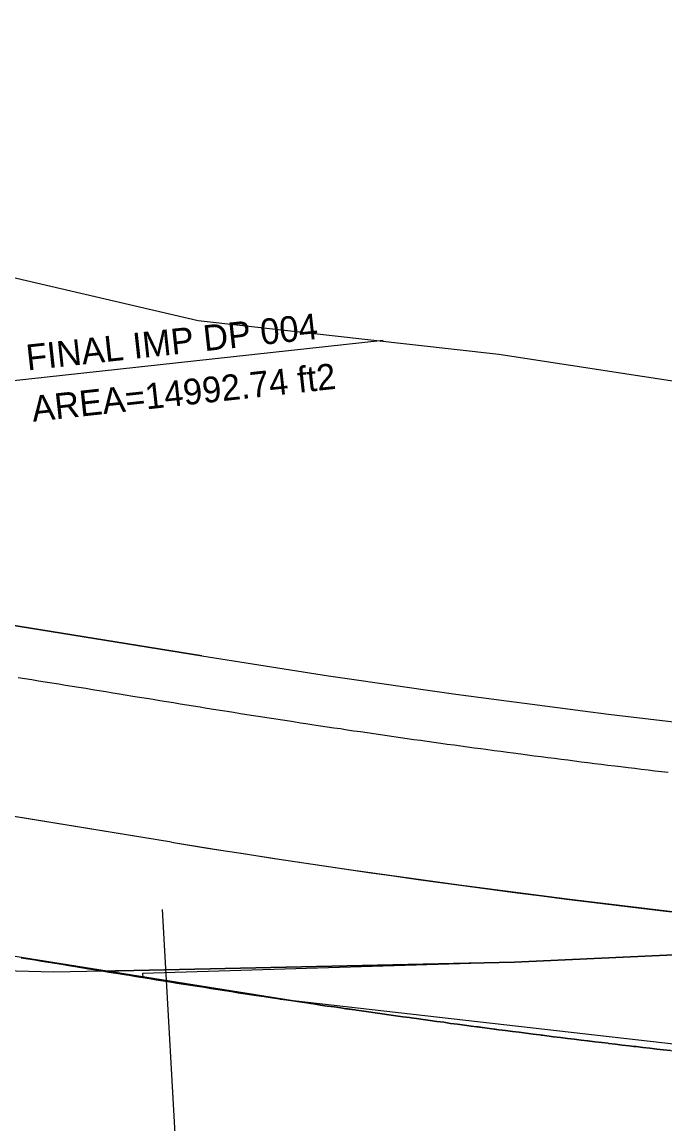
# Model space of a CAD drawing. Extents: x 1509538 to 1510847, y 401283 to 402022.
# Drawn here: x 1510416.9 to 1510486.8, y 401644.9 to 401764.5 of the extents above; entities that cross this region are included whole.
import ezdxf

# ---------------------------------------------------------------- set-up
doc = ezdxf.new("R2010")
doc.units = 0
for name, color, linetype in [('LDEFAULT_P', 7, 'Continuous'), ('Level 14', 7, 'Continuous'), ('Level 19', 7, 'Continuous'), ('Level 2', 7, 'Continuous'), ('Level 20', 7, 'Continuous'), ('Level 23', 7, 'Continuous'), ('Level 24', 7, 'Continuous'), ('Level 3', 7, 'Continuous'), ('Level 4', 7, 'Continuous')]:
    doc.layers.add(name, color=color, linetype=linetype)

msp = doc.modelspace()

# ---------------------------------------------------------------- linework, layer by layer
at = {"layer": 'LDEFAULT_P'}
for points in [[(1510353.52, 401708.78), (1510415.34, 401725.51), (1510456.17, 401729.97)], [(1510432.16, 401668.14), (1510435.57, 401607.93), (1510476.4, 401612.38)]]:
    msp.add_lwpolyline(points, dxfattribs=at)
at = {"layer": 'Level 14'}
for p, q in [((1510311.33, 401716), (1510436.45, 401695.69)), ((1510433.17, 401675.46), (1510308.05, 401695.77))]:
    msp.add_line(p, q, dxfattribs=at)
for centre, radius, start, end in [((1510625.43, 402859.96), 1179.5, 260.78048, 265.11677), ((1510626.3, 402875.58), 1215.57, 260.85794, 272.75803)]:
    msp.add_arc(centre, radius, start, end, dxfattribs=at)
at = {"layer": 'Level 19'}
for points in [[(1510433.17, 401675.46), (1510410.94, 401679.07)], [(1510425.8, 401661.46), (1510470.43, 401662.43), (1510519.22, 401664.67)], [(1510416.84, 401662.91), (1510417.58, 401662.79), (1510418.31, 401662.67), (1510419.04, 401662.55), (1510419.78, 401662.43), (1510420.51, 401662.32), (1510421.24, 401662.2), (1510421.97, 401662.08), (1510422.71, 401661.96), (1510423.34, 401661.86), (1510424.17, 401661.72), (1510424.91, 401661.6), (1510425.8, 401661.46), (1510425.8, 401661.46)]]:
    msp.add_lwpolyline(points, dxfattribs=at)
msp.add_arc((1510625.43, 402859.96), 1200, 260.78048, 264.92169, dxfattribs=at)
at = {"layer": 'Level 2'}
for p, q in [((1510425.8, 401661.46), (1510426.37, 401661.36)), ((1510430.02, 401661.19), (1510430.04, 401660.77)), ((1510432.25, 401660.41), (1510433, 401660.29)), ((1510433, 401660.29), (1510433.74, 401660.17)), ((1510433.74, 401660.17), (1510434.48, 401660.05)), ((1510435.97, 401659.82), (1510436.71, 401659.7)), ((1510436.71, 401659.7), (1510437.45, 401659.58)), ((1510437.45, 401659.58), (1510438.2, 401659.47)), ((1510438.2, 401659.47), (1510438.94, 401659.35)), ((1510438.94, 401659.35), (1510439.68, 401659.24)), ((1510443.25, 401658.69), (1510444.14, 401658.56)), ((1510444.14, 401658.56), (1510444.88, 401658.45)), ((1510446.37, 401658.22), (1510447.11, 401658.11)), ((1510447.11, 401658.11), (1510447.86, 401658)), ((1510447.86, 401658), (1510448.6, 401657.89)), ((1510452.09, 401657.38), (1510453.07, 401657.24)), ((1510458.28, 401656.51), (1510459.02, 401656.41)), ((1510459.02, 401656.41), (1510459.77, 401656.3)), ((1510459.77, 401656.3), (1510460.51, 401656.2)), ((1510460.51, 401656.2), (1510461.26, 401656.1)), ((1510463.29, 401655.82), (1510464.24, 401655.69)), ((1510465.73, 401655.5), (1510466.34, 401655.42)), ((1510466.34, 401655.42), (1510467.22, 401655.3)), ((1510467.22, 401655.3), (1510467.96, 401655.2)), ((1510467.96, 401655.2), (1510468.71, 401655.1)), ((1510471.69, 401654.72), (1510472.44, 401654.63)), ((1510472.44, 401654.63), (1510473.18, 401654.53)), ((1510477.66, 401653.97), (1510478.36, 401653.89)), ((1510479.9, 401653.7), (1510480.61, 401653.62)), ((1510480.61, 401653.62), (1510481.39, 401653.52)), ((1510482.89, 401653.35), (1510483.63, 401653.26))]:
    msp.add_line(p, q, dxfattribs=at)
for points in [[(1510621.58, 401670.53), (1510593.1, 401669.05), (1510591.76, 401675.43), (1510572.55, 401675.82), (1510570.33, 401679.6), (1510568.49, 401681.42), (1510567.15, 401683.24), (1510565.64, 401686.29), (1510548.91, 401687.45), (1510550.67, 401678.74), (1510543.3, 401672.37), (1510525.32, 401669.96), (1510520.33, 401664.72), (1510470.43, 401662.43), (1510425.8, 401661.46)], [(1510520.33, 401664.72), (1510470.43, 401662.43), (1510430.02, 401661.19)], [(1510426.37, 401661.36), (1510427.11, 401661.24), (1510427.84, 401661.13), (1510428.28, 401661.05), (1510428.57, 401661.01), (1510429.3, 401660.89), (1510430.04, 401660.77), (1510430.77, 401660.65), (1510430.77, 401660.65), (1510431.51, 401660.53), (1510432.25, 401660.41), (1510433, 401660.29), (1510433.24, 401660.25), (1510433.74, 401660.17), (1510434.48, 401660.05), (1510435.22, 401659.94), (1510435.97, 401659.82), (1510436.71, 401659.7), (1510437.45, 401659.58), (1510437.87, 401659.52), (1510438.2, 401659.47), (1510438.24, 401659.46), (1510438.94, 401659.35), (1510439.68, 401659.24), (1510440.42, 401659.12), (1510441.17, 401659.01), (1510441.91, 401658.9), (1510442.65, 401658.78), (1510443.25, 401658.69), (1510443.4, 401658.67), (1510444.14, 401658.56), (1510444.88, 401658.45), (1510444.98, 401658.43), (1510445.63, 401658.33), (1510446.37, 401658.22), (1510447.11, 401658.11), (1510447.86, 401658), (1510448.26, 401657.94), (1510448.6, 401657.89), (1510449.35, 401657.78), (1510450.09, 401657.67), (1510450.83, 401657.57), (1510451.58, 401657.46), (1510452.09, 401657.38), (1510452.32, 401657.35), (1510453.07, 401657.24), (1510453.27, 401657.22), (1510453.81, 401657.14), (1510454.56, 401657.03), (1510455.3, 401656.93), (1510456.04, 401656.82), (1510456.79, 401656.72), (1510457.53, 401656.61), (1510458.28, 401656.51), (1510459.02, 401656.41), (1510459.21, 401656.38), (1510459.77, 401656.3), (1510460.51, 401656.2), (1510461.26, 401656.1), (1510462, 401656), (1510462.75, 401655.9), (1510463.29, 401655.82), (1510463.49, 401655.79), (1510464.24, 401655.69), (1510464.98, 401655.6), (1510465.73, 401655.5), (1510466.34, 401655.42), (1510466.47, 401655.4), (1510467.22, 401655.3), (1510467.96, 401655.2), (1510468.31, 401655.16), (1510468.71, 401655.1), (1510469.46, 401655.01), (1510470.2, 401654.91), (1510470.95, 401654.82), (1510471.69, 401654.72), (1510472.44, 401654.63), (1510473.18, 401654.53), (1510473.33, 401654.51), (1510473.47, 401654.5), (1510473.93, 401654.44), (1510474.68, 401654.34), (1510475.42, 401654.25), (1510476.17, 401654.16), (1510476.92, 401654.07), (1510477.66, 401653.97), (1510478.36, 401653.89), (1510478.41, 401653.88), (1510479.15, 401653.79), (1510479.9, 401653.7), (1510480.61, 401653.62), (1510480.65, 401653.61), (1510481.39, 401653.52), (1510482.14, 401653.43), (1510482.89, 401653.35), (1510483.38, 401653.29), (1510483.63, 401653.26), (1510484.38, 401653.17), (1510485.13, 401653.08), (1510485.87, 401653), (1510486.62, 401652.91), (1510487.37, 401652.83)], [(1510430.04, 401660.77), (1510430.77, 401660.65), (1510431.51, 401660.53), (1510432.25, 401660.41)], [(1510434.48, 401660.05), (1510435.22, 401659.94), (1510435.97, 401659.82)], [(1510439.68, 401659.24), (1510440.42, 401659.12), (1510441.17, 401659.01), (1510441.91, 401658.9)], [(1510441.91, 401658.9), (1510442.65, 401658.78), (1510443.25, 401658.69)], [(1510444.88, 401658.45), (1510445.63, 401658.33), (1510446.37, 401658.22)], [(1510448.6, 401657.89), (1510449.35, 401657.78), (1510450.09, 401657.67), (1510450.83, 401657.57), (1510451.58, 401657.46), (1510452.09, 401657.38)], [(1510453.07, 401657.24), (1510453.81, 401657.14), (1510454.56, 401657.03), (1510455.3, 401656.93), (1510456.04, 401656.82)], [(1510456.04, 401656.82), (1510456.79, 401656.72), (1510457.53, 401656.61), (1510458.28, 401656.51)], [(1510461.26, 401656.1), (1510462, 401656), (1510462.75, 401655.9), (1510463.29, 401655.82)], [(1510464.24, 401655.69), (1510464.98, 401655.6), (1510465.73, 401655.5)], [(1510468.71, 401655.1), (1510469.46, 401655.01), (1510470.2, 401654.91), (1510470.95, 401654.82), (1510471.69, 401654.72)], [(1510473.18, 401654.53), (1510473.93, 401654.44), (1510474.68, 401654.34)], [(1510474.68, 401654.34), (1510475.42, 401654.25), (1510476.17, 401654.16)], [(1510476.17, 401654.16), (1510476.92, 401654.07), (1510477.66, 401653.97)], [(1510478.36, 401653.89), (1510479.15, 401653.79), (1510479.9, 401653.7)], [(1510481.39, 401653.52), (1510482.14, 401653.43), (1510482.89, 401653.35)], [(1510483.63, 401653.26), (1510484.38, 401653.17), (1510485.13, 401653.08), (1510485.87, 401653), (1510486.62, 401652.91), (1510487.37, 401652.83), (1510488.11, 401652.74)]]:
    msp.add_lwpolyline(points, dxfattribs=at)
at = {"layer": 'Level 20'}
msp.add_line((1510425.8, 401661.46), (1510426.37, 401661.36), dxfattribs=at)
for points in [[(1510519.22, 401664.67), (1510470.43, 401662.43), (1510425.8, 401661.46)], [(1510426.37, 401661.36), (1510427.11, 401661.24), (1510427.84, 401661.13), (1510428.28, 401661.05), (1510428.57, 401661.01), (1510429.3, 401660.89), (1510430.04, 401660.77), (1510430.77, 401660.65), (1510430.77, 401660.65), (1510431.51, 401660.53), (1510432.25, 401660.41), (1510433, 401660.29), (1510433.24, 401660.25), (1510433.74, 401660.17), (1510434.48, 401660.05), (1510435.22, 401659.94), (1510435.97, 401659.82), (1510436.71, 401659.7), (1510437.45, 401659.58), (1510437.87, 401659.52), (1510438.2, 401659.47), (1510438.24, 401659.46), (1510438.94, 401659.35), (1510439.68, 401659.24), (1510440.42, 401659.12), (1510441.17, 401659.01), (1510441.91, 401658.9), (1510442.65, 401658.78), (1510443.25, 401658.69), (1510443.4, 401658.67), (1510444.14, 401658.56), (1510444.88, 401658.45), (1510444.98, 401658.43), (1510445.63, 401658.33), (1510446.37, 401658.22), (1510447.11, 401658.11), (1510447.86, 401658), (1510448.26, 401657.94), (1510448.6, 401657.89), (1510449.35, 401657.78), (1510450.09, 401657.67), (1510450.83, 401657.57), (1510451.58, 401657.46), (1510452.09, 401657.38), (1510452.32, 401657.35), (1510453.07, 401657.24), (1510453.27, 401657.22), (1510453.81, 401657.14), (1510454.56, 401657.03), (1510455.3, 401656.93), (1510456.04, 401656.82), (1510456.79, 401656.72), (1510457.53, 401656.61), (1510458.28, 401656.51), (1510459.02, 401656.41), (1510459.21, 401656.38), (1510459.77, 401656.3), (1510460.51, 401656.2), (1510461.26, 401656.1), (1510462, 401656), (1510462.75, 401655.9), (1510463.29, 401655.82), (1510463.49, 401655.79), (1510464.24, 401655.69), (1510464.98, 401655.6), (1510465.73, 401655.5), (1510466.34, 401655.42), (1510466.47, 401655.4), (1510467.22, 401655.3), (1510467.96, 401655.2), (1510468.31, 401655.16), (1510468.71, 401655.1), (1510469.46, 401655.01), (1510470.2, 401654.91), (1510470.95, 401654.82), (1510471.69, 401654.72), (1510472.44, 401654.63), (1510473.18, 401654.53), (1510473.33, 401654.51), (1510473.47, 401654.5), (1510473.93, 401654.44), (1510474.68, 401654.34), (1510475.42, 401654.25), (1510476.17, 401654.16), (1510476.92, 401654.07), (1510477.66, 401653.97), (1510478.36, 401653.89), (1510478.41, 401653.88), (1510479.15, 401653.79), (1510479.9, 401653.7), (1510480.61, 401653.62), (1510480.65, 401653.61), (1510481.39, 401653.52), (1510482.14, 401653.43), (1510482.89, 401653.35), (1510483.38, 401653.29), (1510483.63, 401653.26), (1510484.38, 401653.17), (1510485.13, 401653.08), (1510485.87, 401653), (1510486.62, 401652.91), (1510487.37, 401652.83)]]:
    msp.add_lwpolyline(points, dxfattribs=at)
at = {"layer": 'Level 23'}
msp.add_lwpolyline([(1510410.25, 401663.98), (1510406.28, 401635.45), (1510599.09, 401629.32), (1510685.54, 401649.67), (1510635.53, 401647.32), (1510591.21, 401645.44), (1510529.65, 401648.74), (1510446.37, 401658.22)], close=True, dxfattribs=at)
at = {"layer": 'Level 24'}
msp.add_lwpolyline([(1510359.87, 401749.85), (1510436.07, 401732.12), (1510468.72, 401728.44), (1510492.07, 401724.89), (1510498.04, 401725.77), (1510520.27, 401739.91), (1510516.78, 401757.54), (1510553.49, 401764.52), (1510567.6, 401764.22), (1510578.98, 401712.86), (1510608.33, 401698.35), (1510682.71, 401677.22), (1510684.16, 401674.23), (1510685.11, 401648.19), (1510623.85, 401633.39), (1510589.3, 401615.77), (1510582.28, 401611.13), (1510485.41, 401619.76), (1510463.51, 401615.28), (1510452.26, 401619.93), (1510436.45, 401620.31), (1510422.96, 401609.85), (1510373.65, 401595.47)], dxfattribs=at)
at = {"layer": 'Level 3'}
for p, q in [((1510436.45, 401695.69), (1510311.33, 401716)), ((1510416.52, 401693.36), (1510417.25, 401693.24)), ((1510417.25, 401693.24), (1510417.99, 401693.12)), ((1510417.99, 401693.12), (1510418.72, 401693)), ((1510418.72, 401693), (1510419.45, 401692.88)), ((1510419.45, 401692.88), (1510420.18, 401692.76)), ((1510420.18, 401692.76), (1510420.92, 401692.64)), ((1510420.92, 401692.64), (1510421.65, 401692.52)), ((1510421.65, 401692.52), (1510422.38, 401692.4)), ((1510422.38, 401692.4), (1510423.12, 401692.28)), ((1510423.12, 401692.28), (1510423.85, 401692.17)), ((1510423.85, 401692.17), (1510424.58, 401692.05)), ((1510424.58, 401692.05), (1510425.31, 401691.93)), ((1510425.31, 401691.93), (1510426.05, 401691.81)), ((1510426.05, 401691.81), (1510426.78, 401691.69)), ((1510426.78, 401691.69), (1510427.51, 401691.57)), ((1510427.51, 401691.57), (1510428.15, 401691.47)), ((1510428.15, 401691.47), (1510428.98, 401691.33)), ((1510428.98, 401691.33), (1510429.71, 401691.22)), ((1510429.71, 401691.22), (1510430.45, 401691.1)), ((1510430.45, 401691.1), (1510431.18, 401690.98)), ((1510431.18, 401690.98), (1510431.91, 401690.86)), ((1510431.91, 401690.86), (1510432.64, 401690.74)), ((1510432.64, 401690.74), (1510433.38, 401690.62)), ((1510433.38, 401690.62), (1510434.11, 401690.5)), ((1510434.11, 401690.5), (1510434.84, 401690.38)), ((1510434.84, 401690.38), (1510435.57, 401690.26)), ((1510435.57, 401690.26), (1510436.3, 401690.15)), ((1510436.3, 401690.15), (1510437.02, 401690.03)), ((1510437.02, 401690.03), (1510437.75, 401689.91)), ((1510437.75, 401689.91), (1510438.47, 401689.8)), ((1510438.47, 401689.8), (1510439.2, 401689.68)), ((1510439.2, 401689.68), (1510439.92, 401689.57)), ((1510439.92, 401689.57), (1510440.65, 401689.45)), ((1510440.65, 401689.45), (1510441.37, 401689.34)), ((1510441.37, 401689.34), (1510442.09, 401689.22)), ((1510442.09, 401689.22), (1510442.82, 401689.11)), ((1510442.82, 401689.11), (1510443.54, 401689)), ((1510443.54, 401689), (1510444.27, 401688.88)), ((1510444.27, 401688.88), (1510444.99, 401688.77)), ((1510444.99, 401688.77), (1510445.72, 401688.66)), ((1510445.72, 401688.66), (1510446.44, 401688.55)), ((1510446.44, 401688.55), (1510447.17, 401688.44)), ((1510447.17, 401688.44), (1510447.75, 401688.35)), ((1510447.75, 401688.35), (1510448.62, 401688.22)), ((1510448.62, 401688.22), (1510449.34, 401688.11)), ((1510449.34, 401688.11), (1510450.07, 401688)), ((1510450.07, 401688), (1510450.79, 401687.89)), ((1510450.79, 401687.89), (1510451.52, 401687.79)), ((1510451.52, 401687.79), (1510452.24, 401687.68)), ((1510452.24, 401687.68), (1510452.97, 401687.57)), ((1510452.97, 401687.57), (1510453.69, 401687.47)), ((1510453.69, 401687.47), (1510454.42, 401687.36)), ((1510454.42, 401687.36), (1510455.15, 401687.25)), ((1510455.15, 401687.25), (1510455.87, 401687.15)), ((1510455.87, 401687.15), (1510456.6, 401687.04)), ((1510456.6, 401687.04), (1510457.32, 401686.94)), ((1510457.32, 401686.94), (1510458.05, 401686.84)), ((1510458.05, 401686.84), (1510458.77, 401686.73)), ((1510458.77, 401686.73), (1510459.5, 401686.63)), ((1510459.5, 401686.63), (1510460.23, 401686.53)), ((1510460.23, 401686.53), (1510460.95, 401686.43)), ((1510460.95, 401686.43), (1510461.68, 401686.32)), ((1510461.68, 401686.32), (1510462.41, 401686.22)), ((1510462.41, 401686.22), (1510463.13, 401686.12)), ((1510463.13, 401686.12), (1510463.86, 401686.02)), ((1510463.86, 401686.02), (1510464.58, 401685.92)), ((1510464.58, 401685.92), (1510465.31, 401685.82)), ((1510465.31, 401685.82), (1510466.04, 401685.72)), ((1510466.04, 401685.72), (1510466.76, 401685.63)), ((1510466.76, 401685.63), (1510467.3, 401685.55)), ((1510467.3, 401685.55), (1510468.22, 401685.43)), ((1510468.22, 401685.43), (1510468.94, 401685.33)), ((1510468.94, 401685.33), (1510469.67, 401685.24)), ((1510469.67, 401685.24), (1510470.27, 401685.16)), ((1510470.27, 401685.16), (1510471.13, 401685.04)), ((1510471.13, 401685.04), (1510471.85, 401684.95)), ((1510471.85, 401684.95), (1510472.58, 401684.85)), ((1510472.58, 401684.85), (1510473.31, 401684.76)), ((1510473.31, 401684.76), (1510474.03, 401684.67)), ((1510474.03, 401684.67), (1510474.76, 401684.57)), ((1510474.76, 401684.57), (1510475.49, 401684.48)), ((1510475.49, 401684.48), (1510476.22, 401684.39)), ((1510476.22, 401684.39), (1510476.94, 401684.29)), ((1510476.94, 401684.29), (1510477.67, 401684.2)), ((1510477.67, 401684.2), (1510478.4, 401684.11)), ((1510478.4, 401684.11), (1510479.13, 401684.02)), ((1510479.13, 401684.02), (1510479.85, 401683.93)), ((1510479.85, 401683.93), (1510480.58, 401683.84)), ((1510480.58, 401683.84), (1510481.31, 401683.75)), ((1510481.31, 401683.75), (1510481.99, 401683.67)), ((1510481.99, 401683.67), (1510482.77, 401683.57)), ((1510482.77, 401683.57), (1510483.49, 401683.49)), ((1510483.49, 401683.49), (1510484.18, 401683.4)), ((1510484.18, 401683.4), (1510484.95, 401683.31)), ((1510484.95, 401683.31), (1510485.68, 401683.22)), ((1510485.68, 401683.22), (1510486.41, 401683.14)), ((1510486.41, 401683.14), (1510487.13, 401683.05))]:
    msp.add_line(p, q, dxfattribs=at)
for points in [[(1510416.52, 401693.36), (1510417.25, 401693.24), (1510417.99, 401693.12), (1510418.72, 401693), (1510419.45, 401692.88), (1510420.18, 401692.76), (1510420.92, 401692.64), (1510421.65, 401692.52), (1510422.38, 401692.4), (1510423.12, 401692.28), (1510423.85, 401692.17), (1510424.58, 401692.05), (1510425.31, 401691.93), (1510426.05, 401691.81), (1510426.78, 401691.69), (1510427.51, 401691.57), (1510428.15, 401691.47), (1510428.98, 401691.33), (1510429.71, 401691.22), (1510430.45, 401691.1), (1510431.18, 401690.98), (1510431.91, 401690.86), (1510432.64, 401690.74), (1510433.38, 401690.62), (1510434.11, 401690.5), (1510434.84, 401690.38), (1510435.57, 401690.26), (1510436.3, 401690.15), (1510437.02, 401690.03), (1510437.75, 401689.91), (1510438.47, 401689.8), (1510439.2, 401689.68), (1510439.92, 401689.57), (1510440.65, 401689.45), (1510441.37, 401689.34), (1510442.09, 401689.22), (1510442.82, 401689.11), (1510443.54, 401689), (1510444.27, 401688.88), (1510444.99, 401688.77), (1510445.72, 401688.66), (1510446.44, 401688.55), (1510447.17, 401688.44), (1510447.75, 401688.35), (1510448.62, 401688.22), (1510449.34, 401688.11), (1510450.07, 401688), (1510450.79, 401687.89), (1510451.52, 401687.79), (1510452.24, 401687.68), (1510452.97, 401687.57), (1510453.69, 401687.47), (1510454.42, 401687.36), (1510455.15, 401687.25), (1510455.87, 401687.15), (1510456.6, 401687.04), (1510457.32, 401686.94), (1510458.05, 401686.84), (1510458.77, 401686.73), (1510459.5, 401686.63), (1510460.23, 401686.53), (1510460.95, 401686.43), (1510461.68, 401686.32), (1510462.41, 401686.22), (1510463.13, 401686.12), (1510463.86, 401686.02), (1510464.58, 401685.92), (1510465.31, 401685.82), (1510466.04, 401685.72), (1510466.76, 401685.63), (1510467.3, 401685.55), (1510468.22, 401685.43), (1510468.94, 401685.33), (1510469.67, 401685.24), (1510470.27, 401685.16), (1510471.13, 401685.04), (1510471.85, 401684.95), (1510472.58, 401684.85), (1510473.31, 401684.76), (1510474.03, 401684.67), (1510474.76, 401684.57), (1510475.49, 401684.48), (1510476.22, 401684.39), (1510476.94, 401684.29), (1510477.67, 401684.2), (1510478.4, 401684.11), (1510479.13, 401684.02), (1510479.85, 401683.93), (1510480.58, 401683.84), (1510481.31, 401683.75), (1510481.99, 401683.67), (1510482.77, 401683.57), (1510483.49, 401683.49), (1510484.18, 401683.4), (1510484.95, 401683.31), (1510485.68, 401683.22), (1510486.41, 401683.14), (1510487.13, 401683.05)], [(1510520.33, 401664.72), (1510470.43, 401662.43), (1510427.83, 401661.5), (1510427.1, 401661.48), (1510426.37, 401661.47), (1510425.8, 401661.46), (1510424.91, 401661.6), (1510424.17, 401661.72), (1510423.34, 401661.86), (1510422.71, 401661.96), (1510421.97, 401662.08), (1510421.24, 401662.2), (1510420.51, 401662.32), (1510419.78, 401662.43), (1510419.04, 401662.55), (1510418.31, 401662.67), (1510417.58, 401662.79), (1510416.84, 401662.91)]]:
    msp.add_lwpolyline(points, dxfattribs=at)
msp.add_arc((1510625.43, 402859.96), 1179.5, 260.78048, 265.11677, dxfattribs=at)
at = {"layer": 'Level 4'}
for p, q in [((1510425.8, 401661.46), (1510420.35, 401661.34)), ((1510426.37, 401661.36), (1510425.8, 401661.46)), ((1510430.77, 401660.65), (1510430.04, 401660.77)), ((1510431.51, 401660.53), (1510430.77, 401660.65)), ((1510435.97, 401659.82), (1510435.22, 401659.94)), ((1510436.71, 401659.7), (1510435.97, 401659.82)), ((1510437.45, 401659.58), (1510436.71, 401659.7)), ((1510438.24, 401659.46), (1510438.2, 401659.47)), ((1510444.14, 401658.56), (1510443.4, 401658.67)), ((1510444.88, 401658.45), (1510444.14, 401658.56)), ((1510447.86, 401658), (1510447.11, 401658.11)), ((1510448.26, 401657.94), (1510447.86, 401658)), ((1510448.6, 401657.89), (1510448.26, 401657.94)), ((1510456.04, 401656.82), (1510455.3, 401656.93)), ((1510459.77, 401656.3), (1510459.21, 401656.38)), ((1510460.51, 401656.2), (1510459.77, 401656.3)), ((1510461.26, 401656.1), (1510460.51, 401656.2)), ((1510466.34, 401655.42), (1510465.73, 401655.5)), ((1510466.47, 401655.4), (1510466.34, 401655.42)), ((1510472.44, 401654.63), (1510471.69, 401654.72)), ((1510473.18, 401654.53), (1510472.44, 401654.63)), ((1510480.61, 401653.62), (1510479.9, 401653.7)), ((1510485.87, 401653), (1510485.13, 401653.08))]:
    msp.add_line(p, q, dxfattribs=at)
for points in [[(1510420.35, 401661.34), (1510371.76, 401662.64), (1510321.9, 401665.44), (1510271.44, 401667.79), (1510220.39, 401667.36), (1510212.05, 401667), (1510168.51, 401664.21), (1510117.95, 401657.12), (1510069.7, 401647.38)], [(1510430.04, 401660.77), (1510429.3, 401660.89), (1510428.57, 401661.01), (1510428.28, 401661.05), (1510427.84, 401661.13), (1510427.11, 401661.24), (1510426.37, 401661.36)], [(1510433.24, 401660.25), (1510433, 401660.29), (1510432.25, 401660.41), (1510431.51, 401660.53)], [(1510435.22, 401659.94), (1510434.48, 401660.05), (1510433.74, 401660.17), (1510433.24, 401660.25)], [(1510438.2, 401659.47), (1510437.87, 401659.52), (1510437.45, 401659.58)], [(1510441.91, 401658.9), (1510441.17, 401659.01), (1510440.42, 401659.12), (1510439.68, 401659.24), (1510438.94, 401659.35), (1510438.24, 401659.46)], [(1510443.4, 401658.67), (1510443.25, 401658.69), (1510442.65, 401658.78), (1510441.91, 401658.9)], [(1510445.63, 401658.33), (1510444.98, 401658.43), (1510444.88, 401658.45)], [(1510447.11, 401658.11), (1510446.37, 401658.22), (1510445.63, 401658.33)], [(1510450.83, 401657.57), (1510450.09, 401657.67), (1510449.35, 401657.78), (1510448.6, 401657.89)], [(1510452.32, 401657.35), (1510452.09, 401657.38), (1510451.58, 401657.46), (1510450.83, 401657.57)], [(1510455.3, 401656.93), (1510454.56, 401657.03), (1510453.81, 401657.14), (1510453.27, 401657.22), (1510453.07, 401657.24), (1510452.32, 401657.35)], [(1510458.28, 401656.51), (1510457.53, 401656.61), (1510456.79, 401656.72), (1510456.04, 401656.82)], [(1510459.21, 401656.38), (1510459.02, 401656.41), (1510458.28, 401656.51)], [(1510463.29, 401655.82), (1510462.75, 401655.9), (1510462, 401656), (1510461.26, 401656.1)], [(1510464.24, 401655.69), (1510463.49, 401655.79), (1510463.29, 401655.82)], [(1510465.73, 401655.5), (1510464.98, 401655.6), (1510464.24, 401655.69)], [(1510468.31, 401655.16), (1510467.96, 401655.2), (1510467.22, 401655.3), (1510466.47, 401655.4)], [(1510470.2, 401654.91), (1510469.46, 401655.01), (1510468.71, 401655.1), (1510468.31, 401655.16)], [(1510471.69, 401654.72), (1510470.95, 401654.82), (1510470.2, 401654.91)], [(1510477.66, 401653.97), (1510476.92, 401654.07), (1510476.17, 401654.16), (1510475.42, 401654.25), (1510474.68, 401654.34), (1510473.93, 401654.44), (1510473.47, 401654.5), (1510473.33, 401654.51), (1510473.18, 401654.53)], [(1510479.9, 401653.7), (1510479.15, 401653.79), (1510478.41, 401653.88), (1510478.36, 401653.89), (1510477.66, 401653.97)], [(1510482.89, 401653.35), (1510482.14, 401653.43), (1510481.39, 401653.52), (1510480.65, 401653.61), (1510480.61, 401653.62)], [(1510485.13, 401653.08), (1510484.38, 401653.17), (1510483.63, 401653.26), (1510483.38, 401653.29), (1510482.89, 401653.35)], [(1510487.37, 401652.83), (1510486.62, 401652.91), (1510485.87, 401653)]]:
    msp.add_lwpolyline(points, dxfattribs=at)

# ---------------------------------------------------------------- texts
at = {"layer": 'LDEFAULT_P'}
for s, p in [('FINAL IMP DP 004', (1510417.53, 401726.68)), ('AREA=14992.74 ft2', (1510418.13, 401721.11))]:
    msp.add_text(s, height=2.8, rotation=6.2219, dxfattribs=at).set_placement(p)

doc.saveas('drawing.dxf')
